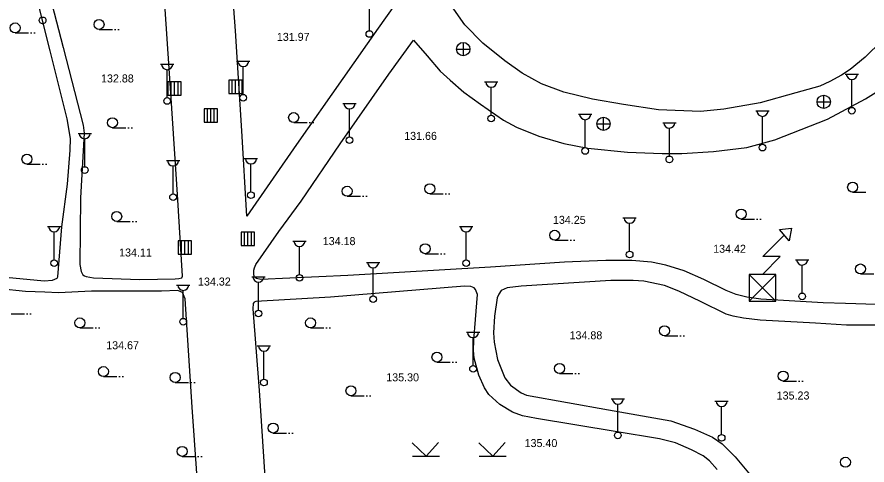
# Model space of a CAD drawing. Extents: x 419101 to 420177, y 4451541 to 4452254.
# Drawn here: x 419292.2 to 419419.6, y 4452109.6 to 4452176.8 of the extents above; entities that cross this region are included whole.
import ezdxf

# ---------------------------------------------------------------- set-up
doc = ezdxf.new("R2010")
doc.units = 0
doc.layers.add('3_HALİHAZIR', color=7, linetype='Continuous')

msp = doc.modelspace()

# ---------------------------------------------------------------- linework, layer by layer
at = {"layer": '3_HALİHAZIR'}
for p, q in [((419345, 4452174.76), (419345, 4452178.95)), ((419291.89, 4452174.42), (419293.89, 4452174.42)), ((419294.19, 4452174.42), (419294.39, 4452174.42)), ((419294.69, 4452174.42), (419294.89, 4452174.42)), ((419304.47, 4452174.95), (419306.47, 4452174.95)), ((419306.77, 4452174.95), (419306.97, 4452174.95)), ((419307.27, 4452174.95), (419307.47, 4452174.95)), ((419359.09, 4452170.98), (419359.09, 4452172.98)), ((419358.07, 4452171.97), (419360.07, 4452171.97)), ((419313.68, 4452169.71), (419315.68, 4452169.71)), ((419325.09, 4452170.2), (419327.09, 4452170.2)), ((419326.09, 4452165.2), (419326.09, 4452169.4)), ((419314.68, 4452164.71), (419314.68, 4452168.91)), ((419416.33, 4452168.25), (419418.33, 4452168.25)), ((419316.77, 4452167.1), (419314.77, 4452167.1)), ((419314.77, 4452167.1), (419314.77, 4452165.1)), ((419316.77, 4452167.1), (419314.77, 4452167.1)), ((419314.77, 4452167.1), (419314.77, 4452165.1)), ((419315.27, 4452165.1), (419315.27, 4452167.1)), ((419315.77, 4452165.1), (419315.77, 4452167.1)), ((419316.31, 4452165.1), (419316.31, 4452167.1)), ((419316.77, 4452165.1), (419316.77, 4452167.1)), ((419316.77, 4452165.1), (419316.77, 4452167.1)), ((419325.91, 4452167.33), (419323.91, 4452167.33)), ((419323.91, 4452167.33), (419323.91, 4452165.33)), ((419325.91, 4452167.33), (419323.91, 4452167.33)), ((419323.91, 4452167.33), (419323.91, 4452165.33)), ((419324.42, 4452165.33), (419324.42, 4452167.33)), ((419324.91, 4452165.33), (419324.91, 4452167.33)), ((419325.46, 4452165.33), (419325.46, 4452167.33)), ((419325.91, 4452165.33), (419325.91, 4452167.33)), ((419325.91, 4452165.33), (419325.91, 4452167.33)), ((419362.27, 4452167.08), (419364.27, 4452167.08)), ((419417.33, 4452163.25), (419417.33, 4452167.44)), ((419323.91, 4452165.33), (419325.91, 4452165.33)), ((419323.91, 4452165.33), (419325.91, 4452165.33)), ((419363.27, 4452162.08), (419363.27, 4452166.28)), ((419314.77, 4452165.1), (419316.77, 4452165.1)), ((419314.77, 4452165.1), (419316.77, 4452165.1)), ((419412.11, 4452164.06), (419414.11, 4452164.06)), ((419413.13, 4452163.07), (419413.13, 4452165.07)), ((419322.21, 4452163.03), (419320.21, 4452163.03)), ((419320.21, 4452163.03), (419320.21, 4452161.03)), ((419322.21, 4452163.03), (419320.21, 4452163.03)), ((419320.21, 4452163.03), (419320.21, 4452161.03)), ((419320.71, 4452161.03), (419320.71, 4452163.03)), ((419321.21, 4452161.03), (419321.21, 4452163.03)), ((419321.75, 4452161.03), (419321.75, 4452163.03)), ((419322.21, 4452161.03), (419322.21, 4452163.03)), ((419322.21, 4452161.03), (419322.21, 4452163.03)), ((419341.02, 4452163.83), (419343.02, 4452163.83)), ((419342.02, 4452158.83), (419342.02, 4452163.03)), ((419402.93, 4452162.71), (419404.93, 4452162.71)), ((419376.35, 4452162.21), (419378.35, 4452162.21)), ((419377.35, 4452157.21), (419377.35, 4452161.41)), ((419380.12, 4452159.77), (419380.12, 4452161.77)), ((419403.93, 4452157.71), (419403.93, 4452161.9)), ((419306.48, 4452160.2), (419308.48, 4452160.2)), ((419308.78, 4452160.2), (419308.98, 4452160.2)), ((419309.28, 4452160.2), (419309.48, 4452160.2)), ((419320.21, 4452161.03), (419322.21, 4452161.03)), ((419320.21, 4452161.03), (419322.21, 4452161.03)), ((419333.65, 4452160.97), (419335.65, 4452160.97)), ((419335.95, 4452160.97), (419336.15, 4452160.97)), ((419336.45, 4452160.97), (419336.65, 4452160.97)), ((419379.1, 4452160.76), (419381.1, 4452160.76)), ((419388.97, 4452160.95), (419390.97, 4452160.95)), ((419389.97, 4452155.95), (419389.97, 4452160.14)), ((419301.32, 4452159.35), (419303.32, 4452159.35)), ((419302.32, 4452154.35), (419302.32, 4452158.54)), ((419314.57, 4452155.27), (419316.57, 4452155.27)), ((419326.25, 4452155.57), (419328.25, 4452155.57)), ((419293.67, 4452154.73), (419295.67, 4452154.73)), ((419295.97, 4452154.73), (419296.17, 4452154.73)), ((419296.47, 4452154.73), (419296.67, 4452154.73)), ((419315.57, 4452150.27), (419315.57, 4452154.46)), ((419327.25, 4452150.57), (419327.25, 4452154.76)), ((419341.66, 4452149.91), (419343.66, 4452149.91)), ((419343.96, 4452149.91), (419344.16, 4452149.91)), ((419344.46, 4452149.91), (419344.66, 4452149.91)), ((419354.06, 4452150.28), (419356.06, 4452150.28)), ((419356.36, 4452150.28), (419356.56, 4452150.28)), ((419356.86, 4452150.28), (419357.06, 4452150.28)), ((419417.45, 4452150.52), (419419.45, 4452150.52)), ((419307.12, 4452146.13), (419309.12, 4452146.13)), ((419309.42, 4452146.13), (419309.62, 4452146.13)), ((419309.92, 4452146.13), (419310.12, 4452146.13)), ((419383.02, 4452146.67), (419385.02, 4452146.67)), ((419400.74, 4452146.49), (419402.74, 4452146.49)), ((419403.04, 4452146.49), (419403.24, 4452146.49)), ((419403.54, 4452146.49), (419403.74, 4452146.49)), ((419296.74, 4452145.38), (419298.74, 4452145.38)), ((419358.5, 4452145.36), (419360.5, 4452145.36)), ((419384.02, 4452141.67), (419384.02, 4452145.86)), ((419297.74, 4452140.38), (419297.74, 4452144.58)), ((419327.78, 4452144.51), (419325.78, 4452144.51)), ((419325.78, 4452144.51), (419325.78, 4452142.51)), ((419327.78, 4452144.51), (419325.78, 4452144.51)), ((419325.78, 4452144.51), (419325.78, 4452142.51)), ((419326.28, 4452142.51), (419326.28, 4452144.51)), ((419326.78, 4452142.51), (419326.78, 4452144.51)), ((419327.32, 4452142.51), (419327.32, 4452144.51)), ((419327.78, 4452142.51), (419327.78, 4452144.51)), ((419327.78, 4452142.51), (419327.78, 4452144.51)), ((419359.5, 4452140.36), (419359.5, 4452144.55)), ((419403.97, 4452140.89), (419407.2, 4452144.06)), ((419318.34, 4452143.24), (419316.34, 4452143.24)), ((419316.34, 4452143.24), (419316.34, 4452141.24)), ((419318.34, 4452143.24), (419316.34, 4452143.24)), ((419316.34, 4452143.24), (419316.34, 4452141.24)), ((419316.85, 4452141.24), (419316.85, 4452143.24)), ((419317.34, 4452141.24), (419317.34, 4452143.24)), ((419317.89, 4452141.24), (419317.89, 4452143.24)), ((419318.34, 4452141.24), (419318.34, 4452143.24)), ((419318.34, 4452141.24), (419318.34, 4452143.24)), ((419325.78, 4452142.51), (419327.78, 4452142.51)), ((419325.78, 4452142.51), (419327.78, 4452142.51)), ((419333.52, 4452143.18), (419335.52, 4452143.18)), ((419334.52, 4452138.18), (419334.52, 4452142.38)), ((419372.78, 4452143.31), (419374.78, 4452143.31)), ((419375.08, 4452143.31), (419375.28, 4452143.31)), ((419375.58, 4452143.31), (419375.78, 4452143.31)), ((419316.34, 4452141.24), (419318.34, 4452141.24)), ((419316.34, 4452141.24), (419318.34, 4452141.24)), ((419353.36, 4452141.29), (419355.36, 4452141.29)), ((419355.66, 4452141.29), (419355.86, 4452141.29)), ((419356.16, 4452141.29), (419356.36, 4452141.29)), ((419344.56, 4452139.98), (419346.56, 4452139.98)), ((419403.95, 4452138.18), (419406.56, 4452140.89)), ((419406.56, 4452140.89), (419403.97, 4452140.89)), ((419408.89, 4452140.39), (419410.89, 4452140.39)), ((419345.56, 4452134.98), (419345.56, 4452139.17)), ((419409.89, 4452135.39), (419409.89, 4452139.59)), ((419327.37, 4452137.83), (419329.37, 4452137.83)), ((419405.95, 4452138.18), (419401.95, 4452134.18)), ((419401.95, 4452138.18), (419405.95, 4452134.18)), ((419418.62, 4452138.25), (419420.62, 4452138.25)), ((419316.1, 4452136.59), (419318.1, 4452136.59)), ((419328.37, 4452132.83), (419328.37, 4452137.02)), ((419317.1, 4452131.59), (419317.1, 4452135.79)), ((419291.32, 4452132.28), (419293.32, 4452132.28)), ((419293.62, 4452132.28), (419293.82, 4452132.28)), ((419294.12, 4452132.28), (419294.32, 4452132.28)), ((419301.6, 4452130.16), (419303.6, 4452130.16)), ((419303.9, 4452130.16), (419304.1, 4452130.16)), ((419304.4, 4452130.16), (419304.6, 4452130.16)), ((419336.18, 4452130.15), (419338.18, 4452130.15)), ((419338.48, 4452130.15), (419338.68, 4452130.15)), ((419338.98, 4452130.15), (419339.18, 4452130.15)), ((419359.54, 4452129.52), (419361.54, 4452129.52)), ((419360.54, 4452124.52), (419360.54, 4452128.71)), ((419389.24, 4452128.98), (419391.24, 4452128.98)), ((419391.54, 4452128.98), (419391.74, 4452128.98)), ((419392.04, 4452128.98), (419392.24, 4452128.98)), ((419328.2, 4452127.47), (419330.2, 4452127.47)), ((419329.2, 4452122.47), (419329.2, 4452126.67)), ((419355.13, 4452125.02), (419357.13, 4452125.02)), ((419357.43, 4452125.02), (419357.63, 4452125.02)), ((419357.93, 4452125.02), (419358.13, 4452125.02)), ((419373.51, 4452123.31), (419375.51, 4452123.31)), ((419375.81, 4452123.31), (419376.01, 4452123.31)), ((419376.31, 4452123.31), (419376.51, 4452123.31)), ((419305.13, 4452122.85), (419307.13, 4452122.85)), ((419307.43, 4452122.85), (419307.63, 4452122.85)), ((419307.93, 4452122.85), (419308.13, 4452122.85)), ((419315.89, 4452121.97), (419317.89, 4452121.97)), ((419318.19, 4452121.97), (419318.39, 4452121.97)), ((419318.69, 4452121.97), (419318.89, 4452121.97)), ((419407.03, 4452122.18), (419409.03, 4452122.18)), ((419409.33, 4452122.18), (419409.53, 4452122.18)), ((419409.83, 4452122.18), (419410.03, 4452122.18)), ((419342.24, 4452119.97), (419344.24, 4452119.97)), ((419344.54, 4452119.97), (419344.74, 4452119.97)), ((419345.04, 4452119.97), (419345.24, 4452119.97)), ((419381.25, 4452119.53), (419383.25, 4452119.53)), ((419382.25, 4452114.53), (419382.25, 4452118.73)), ((419396.81, 4452119.17), (419398.81, 4452119.17)), ((419397.81, 4452114.17), (419397.81, 4452118.36)), ((419330.58, 4452114.38), (419332.58, 4452114.38)), ((419332.88, 4452114.38), (419333.08, 4452114.38)), ((419333.38, 4452114.38), (419333.58, 4452114.38)), ((419353.49, 4452110.93), (419355.34, 4452112.94)), ((419363.49, 4452110.93), (419365.34, 4452112.94)), ((419353.49, 4452110.93), (419351.43, 4452112.92)), ((419363.49, 4452110.93), (419361.43, 4452112.92)), ((419316.93, 4452110.88), (419318.93, 4452110.88)), ((419319.23, 4452110.88), (419319.43, 4452110.88)), ((419319.73, 4452110.88), (419319.93, 4452110.88)), ((419351.47, 4452110.93), (419355.51, 4452110.93)), ((419361.47, 4452110.93), (419365.51, 4452110.93))]:
    msp.add_line(p, q, dxfattribs=at)
for points in [[(419368.65, 4452205.17), (419366.57, 4452204.09), (419363.02, 4452199.08), (419352.29, 4452183.63), (419346.31, 4452175.13), (419341, 4452167.56), (419334.06, 4452157.7), (419326.62, 4452146.91), (419325.88, 4452159.73), (419324.91, 4452174.74), (419323.74, 4452190.85), (419322.57, 4452207.65)], [(419288.36, 4452137.99), (419296.27, 4452137.2), (419297.49, 4452137.34), (419298.22, 4452137.63), (419298.32, 4452137.81), (419298.89, 4452145.31), (419299.72, 4452151.73), (419300.14, 4452156.85), (419300.17, 4452158.56), (419299.69, 4452161.55), (419297.16, 4452171.74), (419294.41, 4452182.72), (419293.79, 4452185.42), (419292.79, 4452190.61), (419291.56, 4452197.29)], [(419295.72, 4452185.39), (419299.09, 4452172.21), (419302.11, 4452160.6), (419302.24, 4452159.38), (419301.69, 4452149.66), (419301.61, 4452139.69), (419301.8, 4452138.63), (419302.06, 4452138.1), (419302.28, 4452137.96), (419302.55, 4452137.89)], [(419317, 4452137.9), (419316.24, 4452150.16), (419315.31, 4452164.63), (419314.4, 4452177.98)], [(419421.84, 4452173.21), (419419.34, 4452170.78), (419417.08, 4452168.93), (419415.8, 4452168.07), (419414.04, 4452167.14), (419412.51, 4452166.43), (419408.93, 4452165.45), (419403.59, 4452163.95), (419398.15, 4452163), (419394.63, 4452162.65), (419388.35, 4452162.89), (419383.12, 4452163.66), (419378.44, 4452164.48), (419374.15, 4452165.54), (419370.81, 4452166.76), (419367.91, 4452168.36), (419365.3, 4452170.22), (419361.99, 4452172.89), (419359.3, 4452175.66), (419356.97, 4452179)], [(419420.97, 4452133.68), (419416.37, 4452133.83), (419413.04, 4452133.93), (419403.67, 4452134.48), (419401.57, 4452134.75), (419399.98, 4452135.16), (419398.49, 4452135.77), (419395.13, 4452137.41), (419392.2, 4452138.71), (419389.46, 4452139.59), (419387.29, 4452140.04), (419384.36, 4452140.27), (419380.43, 4452140.28), (419375.44, 4452140.08), (419374.24, 4452140.03), (419363.15, 4452139.29), (419341.76, 4452138.01), (419328.74, 4452137.42), (419328.07, 4452137.58), (419327.76, 4452137.79), (419327.68, 4452138.13), (419327.66, 4452138.8), (419327.78, 4452139.18), (419328, 4452139.69), (419331.44, 4452144.6), (419334.77, 4452149.17), (419340.62, 4452157.78), (419347.93, 4452168.25), (419351.63, 4452173.31), (419353.66, 4452170.97), (419355.59, 4452168.66), (419357.13, 4452167.31), (419359.15, 4452165.55), (419361.68, 4452163.72), (419365.12, 4452161.34), (419367.05, 4452160.26), (419370.39, 4452158.92), (419374.14, 4452157.85), (419377.74, 4452157.13), (419383.7, 4452156.51), (419388.89, 4452156.32), (419391.84, 4452156.32), (419396.6, 4452156.64), (419401.61, 4452157.24), (419405.76, 4452158.37), (419413.7, 4452161.46), (419419.39, 4452164.52), (419423.51, 4452167.13)], [(419302.55, 4452137.89), (419303.65, 4452137.69), (419310.57, 4452137.43), (419315.91, 4452137.52), (419316.45, 4452137.55), (419316.88, 4452137.67), (419317, 4452137.9)], [(419421.08, 4452130.58), (419416.54, 4452130.55), (419411.9, 4452130.85), (419403.59, 4452131.3), (419401.08, 4452131.6), (419399.56, 4452131.94), (419398.51, 4452132.22), (419394.62, 4452134.1), (419391.4, 4452135.66), (419389.25, 4452136.52), (419386.15, 4452137.18), (419384.56, 4452137.27), (419381.21, 4452137.29), (419367.76, 4452136.44), (419365.66, 4452136.17), (419364.75, 4452135.79), (419364.4, 4452135.24), (419364.18, 4452134.67), (419363.75, 4452131.94), (419363.63, 4452129.41), (419363.7, 4452127.99), (419364.21, 4452125.39), (419365.3, 4452122.66), (419366.17, 4452121.58), (419367.77, 4452120.4), (419368.57, 4452120.08), (419380.86, 4452117.85), (419390.2, 4452116.2), (419393.76, 4452114.97), (419396.44, 4452113.78), (419397.89, 4452112.75), (419399.86, 4452110.82), (419402.36, 4452107.82)], [(419318.43, 4452118.28), (419317.36, 4452134.54), (419316.98, 4452135.48), (419316.27, 4452135.75), (419313.86, 4452135.69), (419303.36, 4452135.67), (419298.38, 4452135.44), (419296.33, 4452135.51), (419293.46, 4452135.62), (419289.55, 4452136.02), (419288.79, 4452136.14)], [(419397.14, 4452108.89), (419395.97, 4452110.21), (419395.04, 4452110.94), (419393.31, 4452111.85), (419390.91, 4452112.89), (419388.5, 4452113.53), (419381.83, 4452114.62), (419370.04, 4452116.57), (419367.96, 4452116.95), (419366.46, 4452117.5), (419364.54, 4452118.66), (419362.9, 4452120.17), (419362.25, 4452121.14), (419361.43, 4452123.05), (419360.71, 4452125.6), (419360.61, 4452126.77), (419360.65, 4452128.32), (419360.92, 4452131.43), (419361.19, 4452135.16), (419360.89, 4452135.93), (419360.72, 4452136.16), (419360.23, 4452136.36), (419359.24, 4452136.44), (419339.18, 4452134.78), (419327.99, 4452134.13), (419327.71, 4452134), (419327.57, 4452133.83), (419327.53, 4452133.04), (419328.46, 4452120.74), (419329.88, 4452099.42)], [(419320.38, 4452091.86), (419319.41, 4452104.08), (419318.43, 4452118.28)]]:
    msp.add_lwpolyline(points, dxfattribs=at)
for points in [[(419406.46, 4452144.91), (419408.28, 4452145.12), (419407.94, 4452143.21)], [(419401.95, 4452134.18), (419405.95, 4452134.18), (419405.95, 4452138.18), (419401.95, 4452138.18)]]:
    msp.add_lwpolyline(points, close=True, dxfattribs=at)
for centre, radius in [((419296.02, 4452176.31), 0.5), ((419291.89, 4452175.17), 0.75), ((419304.47, 4452175.7), 0.75), ((419345, 4452174.26), 0.5), ((419359.07, 4452171.99), 1), ((419326.09, 4452164.7), 0.5), ((419314.68, 4452164.21), 0.5), ((419413.11, 4452164.08), 1), ((419417.33, 4452162.75), 0.5), ((419306.48, 4452160.95), 0.75), ((419333.65, 4452161.72), 0.75), ((419363.27, 4452161.58), 0.5), ((419380.1, 4452160.78), 1), ((419342.02, 4452158.33), 0.5), ((419403.93, 4452157.21), 0.5), ((419377.35, 4452156.71), 0.5), ((419293.67, 4452155.48), 0.75), ((419389.97, 4452155.45), 0.5), ((419302.32, 4452153.85), 0.5), ((419341.66, 4452150.66), 0.75), ((419354.06, 4452151.03), 0.75), ((419417.45, 4452151.27), 0.75), ((419315.57, 4452149.77), 0.5), ((419327.25, 4452150.07), 0.5), ((419307.12, 4452146.88), 0.75), ((419400.74, 4452147.24), 0.75), ((419372.78, 4452144.06), 0.75), ((419353.36, 4452142.04), 0.75), ((419384.02, 4452141.17), 0.5), ((419297.74, 4452139.88), 0.5), ((419359.5, 4452139.86), 0.5), ((419418.62, 4452139), 0.75), ((419334.52, 4452137.68), 0.5), ((419345.56, 4452134.48), 0.5), ((419409.89, 4452134.89), 0.5), ((419328.37, 4452132.33), 0.5), ((419301.6, 4452130.91), 0.75), ((419317.1, 4452131.09), 0.5), ((419336.18, 4452130.9), 0.75), ((419389.24, 4452129.73), 0.75), ((419355.13, 4452125.77), 0.75), ((419360.54, 4452124.02), 0.5), ((419373.51, 4452124.06), 0.75), ((419305.13, 4452123.6), 0.75), ((419315.89, 4452122.72), 0.75), ((419407.03, 4452122.93), 0.75), ((419329.2, 4452121.97), 0.5), ((419342.24, 4452120.72), 0.75), ((419330.58, 4452115.13), 0.75), ((419382.25, 4452114.03), 0.5), ((419397.81, 4452113.67), 0.5), ((419316.93, 4452111.63), 0.75), ((419416.37, 4452110), 0.75)]:
    msp.add_circle(centre, radius, dxfattribs=at)
for centre in [(419314.68, 4452169.74), (419326.09, 4452170.23), (419417.33, 4452168.28), (419363.27, 4452167.11), (419342.02, 4452163.86), (419403.93, 4452162.74), (419377.35, 4452162.24), (419389.97, 4452160.98), (419302.32, 4452159.38), (419315.57, 4452155.3), (419327.25, 4452155.6), (419384.02, 4452146.69), (419297.74, 4452145.41), (419359.5, 4452145.39), (419334.52, 4452143.21), (419345.56, 4452140.01), (419409.89, 4452140.42), (419328.37, 4452137.86), (419317.1, 4452136.62), (419360.54, 4452129.54), (419329.2, 4452127.5), (419382.25, 4452119.56), (419397.81, 4452119.2)]:
    msp.add_arc(centre, 0.837, 183.298, 356.9072, dxfattribs=at)

# ---------------------------------------------------------------- texts
for s, p in [('131.97 ', (419331.13, 4452173.23)), ('132.88 ', (419304.77, 4452166.99)), ('131.66 ', (419350.22, 4452158.37)), ('134.25 ', (419372.52, 4452145.77)), ('134.18 ', (419338.01, 4452142.58)), ('134.42 ', (419396.54, 4452141.43)), ('134.11 ', (419307.48, 4452140.87)), ('134.32 ', (419319.31, 4452136.51)), ('134.88 ', (419375.01, 4452128.45)), ('134.67 ', (419305.55, 4452126.95)), ('135.30 ', (419347.53, 4452122.14)), ('135.23 ', (419406.06, 4452119.41)), ('135.40 ', (419368.27, 4452112.27))]:
    msp.add_text(s, height=1.2, rotation=359.998, dxfattribs=at).set_placement(p)

doc.saveas('drawing.dxf')
